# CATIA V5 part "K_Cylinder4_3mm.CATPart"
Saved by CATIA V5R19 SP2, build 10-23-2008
Part number: Cylinder4
Bounding box of the stored display mesh (mm): x 0 to 4, y -0.5 to 0.5, z -0.5 to 0.5
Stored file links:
  G:\Khaled_CFAO_2011\ST2M\ST2M_GR1\bgaltie\bgaltie\Khaled\CAD_thinkMOTION\K_Cylinder4_3mm.CATPart
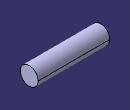
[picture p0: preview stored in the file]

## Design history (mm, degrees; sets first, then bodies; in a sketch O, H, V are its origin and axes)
AxisSystem1: origin (0, 0, 0), X (1, 0, 0), Y (0, 1, 0), Z (0, 0, 1)
Body1 (main body)
  Sketch1 on YZ plane of AxisSystem1, origin (0, 0, 0), H (0, 1, 0), V (0, 0, 1)
    circle A1 centre (0, 0) radius 0.5
    radius A1 = 0.5
  Pad1: profile Sketch1, direction (1, 0, 0), length 4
